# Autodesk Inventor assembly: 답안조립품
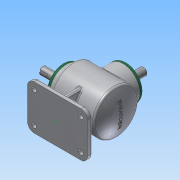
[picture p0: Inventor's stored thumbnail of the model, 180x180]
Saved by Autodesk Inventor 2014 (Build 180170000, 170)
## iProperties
Created: 2016-09
Part Number: 답안조립품
Document SubType Name: Assembly
Designer: 406-05
Author: 406-05
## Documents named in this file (14)
- C:\Users\406-05\Desktop\460907V1003\답안조립품.iam
- C:\Users\406-05\Desktop\460907V1003\본체.ipt
- C:\Users\406-05\Desktop\460907V1003\베어링 6203.ipt
- C:\Users\406-05\Desktop\460907V1003\서브 베벨기어.ipt
- C:\Users\406-05\Desktop\460907V1003\서브 축.ipt
- 서브 축.ipt
- C:\Users\406-05\Desktop\460907V1003\오일실 17 32 8.ipt
- C:\Users\406-05\Desktop\460907V1003\커버.ipt
- C:\Users\406-05\Desktop\460907V1003\키 4x4.ipt
- C:\Users\406-05\Desktop\460907V1003\메인 베벨기어.ipt
- C:\Users\406-05\Desktop\460907V1003\메인 축.ipt
- 메인 축.ipt
- C:\Users\406-05\Desktop\460907V1003\키 5x5.ipt
- C:\Users\406-05\Desktop\460907V1003\M4.ipt
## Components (8 placed, 1 different names)
1. M4:1
2. M4:2
3. M4:3
4. M4:4
5. M4:5
6. M4:6
7. M4:7
8. M4:8
